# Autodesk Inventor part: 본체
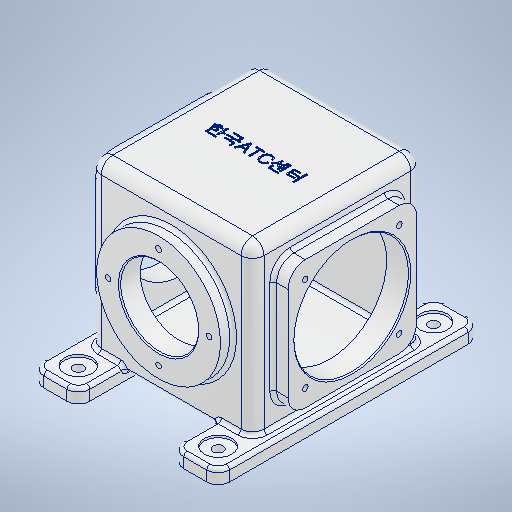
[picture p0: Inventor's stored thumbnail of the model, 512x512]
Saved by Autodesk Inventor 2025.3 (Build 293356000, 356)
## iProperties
Created: 2026-01
Part Number: 본체
Material: 알루미늄 6061
Document SubType Name: Modeling
Designer: PC-13
Density: 2.7 g/cm^3
Appearance: 알루미늄 - 평지
Mass: 2882.07 g
Surface Area: 2447.66 cm^2
Volume: 1067.43 cm^3
Author: PC-13
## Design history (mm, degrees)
sketch "스케치1"
  geometry: L1 (71, -114)-(51, -114); L2 (41, -104)-(41, 104); L3 (51, 114)-(71, 114); L4 (81, 104)-(81, -104); L5 (0, -162.499)-(0, 162.499) reference; L6 (-41, -104)-(-41, 104); L7 (-51, 114)-(-71, 114); L8 (-81, 104)-(-81, -104); L9 (-71, -114)-(-51, -114); L10 (116.299, 0)-(-116.299, 0) reference; A1 r 10 centre (71, -104) between (71, -114) and (81, -104); A2 r 10 centre (51, -104) between (41, -104) and (51, -114); A3 r 10 centre (71, 104) between (81, 104) and (71, 114); A4 r 10 centre (51, 104) between (51, 114) and (41, 104); A5 r 10 centre (-51, 104) between (-41, 104) and (-51, 114); A6 r 10 centre (-71, 104) between (-71, 114) and (-81, 104); A7 r 10 centre (-51, -104) between (-51, -114) and (-41, -104); A8 r 10 centre (-71, -104) between (-81, -104) and (-71, -114); 8 further points
  constraints: 16 end point, 16 point on circle, 16 point on line, 16 tangent, 8 centre point, 7 equal radius, 4 symmetric about line, 2 parallel, 1 horizontal, 1 perpendicular, 1 other
  dimensions: "d5" = 162 distance between parallel lines of L8 L4; "d6" = 40 distance between parallel lines of L2 L4; "d7" = 228 distance between parallel lines of L3 L1; "d8" = 10 radius of A1
extrude "돌출1" new body sketch "스케치1" distance "d9" = 12; taper "d10" = 0 deg
sketch "스케치2"
  geometry: L1 (-71, 156)-(71, 156); L2 (71, 156)-(71, 8); L3 (71, 8)-(-71, 8); L4 (-71, 8)-(-71, 156); L5 (0, -31.2)-(0, 187.2) reference; 1 further point
  constraints: 8 end point, 2 parallel, 1 horizontal, 1 perpendicular, 1 other
  dimensions: "d11" = 156 distance from line of point (0, 0) L1; "d12" = 142 distance between parallel lines of L2 L4; "d13" = 8 distance from line of point (0, 0) L3
extrude "돌출2" join sketch "스케치2" stored distance "d14" = 148; taper "d15" = 0 deg
sketch "스케치3"
  geometry: L1 (-130, 126)-(-18, 126); L2 (-18, 126)-(-18, 14); L3 (-18, 14)-(-130, 14); L4 (-130, 14)-(-130, 126); L5 (-178, -12)-(30, -12) reference; 3 further points
  constraints: 8 end point, 3 midpoint, 2 parallel, 1 horizontal, 1 perpendicular, 1 vertical alignment
  dimensions: "d18" = 112 distance of L2.end L3.end; "d19" = 112 distance of L1.end L2.end; "d20" = 82 vertical distance of point (-74, -12) point (-18, 70)
extrude "돌출3" join sketch "스케치3" distance "d21" = 13; taper "d22" = 0 deg
sketch "스케치4"
  geometry: C1 r 50 at (-74, 70); 1 further point
  constraints: 1 centre point, 1 vertical alignment
  dimensions: "d23" = 100 diameter of C1; "d24" = 82 distance of point (-74, -12) C1.centre
extrude "돌출4" cut sketch "스케치4" extent not by distance; stored distance "d25" = 0; taper "d26" = 0 deg
fillet "모깎기1" dims "d27" = 15
sketch "스케치6"
  geometry: L1 (-115, 29)-(-33, 29); L2 (-33, 29)-(-33, 111); L3 (-33, 111)-(-115, 111); L4 (-115, 111)-(-115, 29); L5 (-115, 29)-(-33, 111); L6 (-33, 29)-(-115, 111); 6 further points
  constraints: 12 end point, 4 coincident, 2 midpoint, 2 parallel, 1 horizontal, 1 perpendicular, 1 vertical alignment
  dimensions: "d46" = 82 distance of L3.end L2.end; "d47" = 82 distance of L2.end L1.end; "d48" = 82 distance of point (-74, -12) point (-74, 70)
hole "구멍2" sketch "스케치6" at (-115, 111), (-33, 111), (-33, 29), (-115, 29) diameter "d39" = 4.917; stored, may be unused: countersink angle "d43" = 90 deg, drill point angle "d45" = 118 deg; dims "d40" = 12, "d41" = 4, "d42" = 2, "d44" = 14
sketch "스케치7"
  geometry: C1 r 54 at (0, 82); C2 r 34 at (0, 82); 1 further point
  constraints: 2 centre point, 1 coincident, 1 vertical alignment
  dimensions: "d49" = 108 diameter of C1; "d50" = 82 distance of point (0, 0) C1.centre; "d51" = 68 diameter of C2
extrude "돌출5" join sketch "스케치7" distance "d52" = 11; taper "d53" = 0 deg
extrude "돌출6" cut sketch "스케치7" stored distance "d54" = 11; taper "d55" = 0 deg
sketch "스케치8" dims "d63" = 88
  geometry: C1 r 34 at (0, 0) reference; 3 further points
  constraints: 2 vertical alignment, 3 other
hole "구멍3" sketch "스케치8" at (0, 44) diameter "d56" = 4.917; stored, may be unused: countersink angle "d60" = 90 deg, drill point angle "d62" = 118 deg; dims "d57" = 12, "d58" = 4, "d59" = 2, "d61" = 14
sketch "스케치9"
  geometry: L1 (-113.4, 0)-(113.4, 0) reference; L2 (0, 159.6)-(0, -159.6) reference; 5 further points
  constraints: 2 horizontal alignment, 2 symmetric about line, 2 vertical alignment
  dimensions: "d74" = 188 distance of point (61, -94) point (61, 94); "d75" = 122 distance of point (61, -94) point (-61, -94)
hole "구멍4" sketch "스케치9" at (61, -94), (-61, -94), (61, 94), (-61, 94) diameter "d67" = 9; stored, may be unused: countersink angle "d71" = 90 deg, drill point angle "d73" = 118 deg; dims "d68" = 12, "d69" = 24, "d70" = 2, "d72" = 14
chamfer "모따기1" distance "d76" = 1; stored, may be unused: second distance "d77" = 2, angle "d78" = 45 deg
fillet "모깎기2" dims "d79" = 3
fillet "모깎기3" dims "d80" = 10
fillet "모깎기4" dims "d81" = 3
fillet "모깎기5" dims "d82" = 3
node "작업 평면1"
sketch "스케치11"
  geometry: L1 (122, 0)-(122, -128) reference; L2 (0, 0)-(122, 0) reference; L3 (0, -128)-(0, 0) reference; L4 (122, -128)-(0, -128) reference; 2 further points
  constraints: 1 coincident, 1 other
feature "엠보싱1" sketch "스케치11" dims "d5" = 162, "d6" = 40, "d7" = 228, "d8" = 10, "d84" = 0.5, "d85" = 0
sketch "스케치12"
  geometry: L1 (156, 64)-(156, -64) reference; L2 (146, -74)-(15, -74) reference; L3 (9, -74)-(15, -74) reference; L4 (8, -77)-(8, 77) reference; L5 (9, -74)-(8, -74) reference; L6 (15, 74)-(146, 74) reference; L7 (15, 74)-(9, 74) reference; L8 (8, 74)-(9, 74) reference; L9 (15, 67)-(146, 67); L10 (149, 64)-(149, -64); L11 (146, -67)-(15, -67); L12 (15, -67)-(15, 67); A1 r 10 centre (146, 64) between (156, 64) and (146, 74) reference; A2 r 10 centre (146, -64) between (146, -74) and (156, -64) reference; A3 r 3 centre (146, 64) between (149, 64) and (146, 67); A4 r 3 centre (146, -64) between (146, -67) and (149, -64); 1 further point
  constraints: 10 end point, 4 point on circle, 2 centre point, 1 parallel, 4 other
  dimensions: "d88" = 7 distance between parallel lines of L10 L1; "d89" = 7 distance between parallel lines of L4 L12
extrude "돌출7" cut sketch "스케치12" stored distance "d90" = 128; taper "d91" = 0 deg
fillet "모깎기6" dims "d92" = 3
fillet "모깎기7" dims "d93" = 3
chamfer "모따기2" distance "d94" = 1; stored, may be unused: second distance "d95" = 2, angle "d96" = 45 deg
node "솔리드1"
pattern_circular "원형 패턴1" dims angle "d65" = 360 deg
mirror "미러2"
node "투영된 루프2"
feature "A9D066F2-1C7D-4E18-AEED-F7BC21143FA4" dims "d56" = 4.917, "d57" = 12, "d58" = 4, "d59" = 2, "d60" = 90 deg, "d61" = 14, "d62" = 118 deg
other parameters: "d83" = 51.75, "d87" = 7
